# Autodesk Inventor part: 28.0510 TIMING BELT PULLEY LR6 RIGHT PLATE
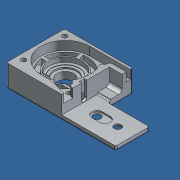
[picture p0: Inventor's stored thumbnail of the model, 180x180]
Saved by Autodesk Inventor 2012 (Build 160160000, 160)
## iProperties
Created: 2007-06
Part Number: 28.0510 TIMING BELT PULLEY LR6 RIGHT PLATE
Document SubType Name: Modeling
Designer: Andy Moles
Material: Aluminum-6061
Mass: 286.09 g
Surface Area: 351.443 cm^2
Volume: 105.568 cm^3
Density: 2.71 g/cm^3
Author: Andy Moles
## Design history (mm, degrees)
sketch "Sketch1"
  geometry: L1 (-35, -39.5)-(-35, 34); L2 (-35, 34)-(51, 34); L3 (51, 34)-(51, 3); L4 (51, 3)-(103, 3); L5 (103, 3)-(103, -39.5); L6 (103, -39.5)-(-35, -39.5); C1 r 10.5 at (0, 0); C2 r 4.5 at (83, -17); C3 r 4.5 at (57, -17); C4 r 3.1 at (-27, 26); C5 r 3.1 at (27, 22.5); C6 r 3.1 at (-27, -26); C7 r 3.1 at (27, -22.5); 1 further point
  constraints: 12 end point, 7 centre point, 4 parallel, 2 vertical alignment, 1 coincident, 1 horizontal alignment, 1 perpendicular, 1 vertical
  dimensions: "d0" = 73.5 distance of L1.start L1.end; "d1" = 138 distance of L5.end L1.start; "d2" = 86 distance of L1.end L2.end; "d3" = 42.5 distance of L4.end L5.end; "d4" = 21 diameter of C1; "d5" = 35 distance from line of point (0, 0) L1; "d6" = 39.5 distance from line of point (0, 0) L6; "d7" = 9 diameter of C3; "d8" = 9 diameter of C2; "d9" = 22.5 distance from line of L6 C2.centre; "d10" = 6.2 diameter of C7; "d11" = 6.2 diameter of C5; "d12" = 6.2 diameter of C4; "d13" = 6.2 diameter of C6; "d14" = 20 distance from line of C2.centre L5; "d15" = 26 distance of C3.centre C2.centre; "d16" = 17 distance from line of L6 C7.centre; "d17" = 45 distance of C5.centre C7.centre; "d18" = 13.5 distance from line of C6.centre L6; "d19" = 52 distance of C4.centre C6.centre; "d20" = 54 horizontal distance of C5.centre C4.centre; "d21" = 8 distance from line of C4.centre L1
extrude "Extrusion1" new body sketch "Sketch1" distance "d22" = 28.5; taper "d23" = 0 deg
hole "Hole1" diameter "d26" = 8; stored, may be unused: countersink angle "d30" = 90 deg, drill point angle "d32" = 118 deg; dims "d24" = 10, "d25" = 10, "d27" = 6, "d28" = 17.5, "d29" = 2, "d31" = 8
hole "Hole2" diameter "d35" = 8; stored, may be unused: countersink angle "d39" = 90 deg, drill point angle "d41" = 118 deg; dims "d33" = 10, "d34" = 10, "d36" = 6, "d37" = 17.5, "d38" = 2, "d40" = 8
sketch "Sketch2"
  geometry: L1 (51, 34)-(51, 3) reference; L2 (-27, 31.976)-(-21.825, 28.988); L3 (-21.825, 28.988)-(-21.825, 23.012); L4 (-21.825, 23.012)-(-27, 20.024); L5 (-27, 20.024)-(-32.175, 23.012); L6 (-32.175, 23.012)-(-32.175, 28.988); L7 (-32.175, 28.988)-(-27, 31.976); L8 (32.175, 19.512)-(27, 16.524); L9 (27, 28.476)-(32.175, 25.488); L10 (21.825, 25.488)-(27, 28.476); L11 (21.825, 19.512)-(21.825, 25.488); L12 (27, 16.524)-(21.825, 19.512); L13 (32.175, 25.488)-(32.175, 19.512); L14 (-21.825, -28.988)-(-27, -31.976); L15 (-21.825, -23.012)-(-21.825, -28.988); L16 (-27, -20.024)-(-21.825, -23.012); L17 (-32.175, -23.012)-(-27, -20.024); L18 (-32.175, -28.988)-(-32.175, -23.012); L19 (-27, -31.976)-(-32.175, -28.988); L20 (32.175, -25.488)-(27, -28.476); L21 (32.175, -19.512)-(32.175, -25.488); L22 (27, -16.524)-(32.175, -19.512); L23 (21.825, -19.512)-(27, -16.524); L24 (21.825, -25.488)-(21.825, -19.512); L25 (27, -28.476)-(21.825, -25.488); C1 r 3.1 at (27, -22.5) reference; C2 r 3.1 at (-27, -26) reference; C3 r 3.1 at (27, 22.5) reference; C4 r 3.1 at (-27, 26) reference; 4 further points
  constraints: 48 end point, 20 equal length, 12 horizontal alignment, 4 midpoint, 4 vertical alignment, 1 parallel
  dimensions: "d42" = 10.35 distance between parallel lines of L4 L7; "d43" = 120 deg angle of L2 L7; "d44" = 10.35 distance between parallel lines of L8 L10; "d45" = 120 deg angle of L9 L10; "d46" = 120 deg angle of L13 L9; "d47" = 10.35 distance between parallel lines of L14 L17; "d48" = 120 deg angle of L16 L17; "d49" = 120 deg angle of L15 L16; "d50" = 10.35 distance between parallel lines of L20 L23; "d51" = 120 deg angle of L22 L23; "d52" = 120 deg angle of L21 L22
extrude "Extrusion2" cut sketch "Sketch2" distance "d53" = 6.1; taper "d54" = 0 deg
sketch "Sketch3"
  geometry: C1 r 10.5 at (0, 0) reference; C2 r 14.3 at (0, 0)
  constraints: 1 centre point, 1 coincident
  dimensions: "d55" = 28.6 diameter of C2
extrude "Extrusion3" cut sketch "Sketch3" distance "d56" = 19.5; taper "d57" = 0 deg
sketch "Sketch4"
  geometry: C1 r 14.3 at (0, 0) reference; C2 r 17.5 at (0, 0)
  constraints: 1 centre point, 1 coincident
  dimensions: "d58" = 35 diameter of C2
extrude "Extrusion4" cut sketch "Sketch4" distance "d59" = 17.5; taper "d60" = 0 deg
sketch "Sketch5"
  geometry: C1 r 17.5 at (0, 0) reference; C2 r 21 at (0, 0)
  constraints: 1 centre point, 1 coincident
  dimensions: "d61" = 42 diameter of C2
extrude "Extrusion5" cut sketch "Sketch5" distance "d62" = 17; taper "d63" = 0 deg
sketch "Sketch6"
  geometry: L1 (35, -39.5)-(35, 34) reference; L2 (-51, 34)-(-51, 3) reference; L3 (-51, 3)-(-103, 3) reference; L4 (-103, 3)-(-103, -39.5) reference; L5 (-103, -39.5)-(35, -39.5) reference; L6 (-51, 20.5)-(-35, 20.5); L7 (-35, 20.5)-(-35, -39.5); C1 r 4.5 at (-57, -17) reference; C2 r 4.5 at (-83, -17) reference
  constraints: 4 end point, 2 point on line, 1 parallel, 1 perpendicular
  dimensions: "d64" = 70 distance between parallel lines of L7 L1; "d65" = 60 distance between parallel lines of L5 L6
extrude "Extrusion6" cut sketch "Sketch6" distance "d66" = 22.5; taper "d67" = 0 deg
fillet "Fillet1" dims "d68" = 2
sketch "Sketch7"
  geometry: L1 (0, 0)-(22.5, 0) reference; L2 (0, -17.5)-(-4, -17.5) reference; L3 (0, -17.5)-(0, -15.5) reference; L4 (2.5, -14.5)-(2.5, -4.5); L5 (0, -15.842)-(0, 0); L6 (0, 0)-(7, 0); A1 r 3 centre (2.5, -17.5) between (2.5, -14.5) and (-0.5, -17.5); A2 r 4.5 centre (7, -4.5) between (7, 0) and (2.5, -4.5); 1 further point
  constraints: 6 end point, 5 point on circle, 3 point on line, 3 tangent, 2 centre point, 2 collinear, 1 horizontal alignment, 1 parallel, 1 vertical alignment
  dimensions: "d69" = 6 diameter of A1; "d70" = 2.5 distance from line of L3 A1.centre; "d71" = 9 diameter of A2
extrude "Extrusion7" join sketch "Sketch7" distance "d72" = 16; taper "d73" = 0 deg
sketch "Sketch8"
  geometry: L1 (-66.982, -10.307)-(-57, -10.307); L2 (-66.982, -23.693)-(-57, -23.693); C1 r 4.5 at (-57, -17) reference; A1 r 6.693 centre (-57, -17) between (-57, -23.693) and (-57, -10.307); A2 r 6.693 centre (-66.982, -17) between (-66.982, -10.307) and (-66.982, -23.693); 1 further point
  constraints: 4 end point, 4 point on circle, 3 tangent, 2 centre point, 1 coincident, 1 horizontal, 1 parallel
  dimensions: "d75" = 13.3858 diameter of A1; "d76" = 13.3858 diameter of A2 (= d75); "d77" = 23.368 dimension on A1 A2
extrude "Extrusion8" cut sketch "Sketch8" distance "d78" = 2; taper "d79" = 0 deg
sketch "Sketch9"
  geometry: L1 (-51, 32)-(-51, 20.5) reference; L2 (-51, 20.5)-(-35, 20.5) reference; L3 (-35, 20.5)-(-35, -39.5) reference; L4 (-35, -39.5)-(33, -39.5) reference; L5 (0, 31)-(-51, 31); L6 (0, -31)-(-12.5, -31); L7 (-35, -37)-(-12.5, -31); L8 (-51, 25.8)-(-33.093, 25.8); L9 (33, 34)-(-49, 34) reference; L10 (-30.1, -22.5)-(-30.1, -22.1); L11 (-35, -25.6)-(-33.6, -25.6); C1 r 21 at (0, 0) reference; A1 r 3.1 centre (-27, 22.5) between (-30.096, 22.652) and (-28.263, 19.669) reference; A2 r 3.1 centre (-27, -22.5) between (-30.1, -22.5) and (-28.263, -19.669) reference; A3 r 3 centre (-29.486, -16.929) between (-28.263, -19.669) and (-26.884, -15.436); A4 r 3 centre (-29.486, 16.929) between (-26.884, 15.436) and (-28.263, 19.669); A5 r 3 centre (-33.093, 22.8) between (-30.096, 22.652) and (-33.093, 25.8); A6 r 3.109 centre (-33.093, 22.8) between (-35.184, 20.5) and (-35, 20.345); A7 r 31 centre (0, 0) between (-26.884, 15.436) and (-26.884, -15.436); A8 r 31 centre (0, 0) between (0, -31) and (0, 31); A9 r 3.5 centre (-33.6, -22.1) between (-33.6, -25.6) and (-30.1, -22.1)
  constraints: 18 point on circle, 12 end point, 11 tangent, 7 centre point, 6 point on line, 3 perpendicular, 2 parallel, 1 coincident
  dimensions: "d81" = 2.5 distance from line of L7.start L4; "d82" = 22.5 distance from line of L6.end L3; "d84" = 6 diameter of A3; "d85" = 6 diameter of A4; "d88" = 3 radius of A5; "d89" = 0.2 distance edge to line of A1 L8; "d90" = 31 radius of A8; "d91" = 31 radius of A7; "d155" = 13.9 distance between parallel lines of L11 L4; "d156" = 3.5 radius of A9
extrude "Extrusion9" cut sketch "Sketch9" distance "d92" = 11; taper "d93" = 0 deg
sketch "Sketch11"
  geometry: L1 (0, -2)-(26.5, -2) reference; L2 (28.5, 0)-(28.5, 69.5) reference; C1 r 2.05 at (19, 26); 1 further point
  constraints: 1 centre point
  dimensions: "d96" = 4.1 diameter of C1; "d97" = 9.5 distance from line of C1.centre L2; "d98" = 28 distance from line of C1.centre L1
extrude "Extrusion10" cut sketch "Sketch11" stored distance "d99" = 11; taper "d100" = 0 deg
hole "Hole3" diameter "d103" = 6.5; stored, may be unused: countersink angle "d107" = 90 deg, drill point angle "d109" = 0 deg; dims "d101" = 10, "d102" = 10, "d104" = 6, "d105" = 17.5, "d106" = 2, "d108" = 25
sketch "Sketch12"
  geometry: L1 (-26, -15.031)-(-10, -15.031); L2 (-10, -15.031)-(-10, -8.031); L3 (-10, -8.031)-(-26, -8.031); L4 (-26, -8.031)-(-26, -15.031); L5 (-10, -9.512)-(-10, -13.55) reference; L6 (-35, 20.5)-(-35, -28.769) reference; 3 further points
  constraints: 8 end point, 3 midpoint, 2 parallel, 1 horizontal, 1 horizontal alignment, 1 perpendicular
  dimensions: "d110" = 7 distance of L3.end L1.start; "d111" = 9 distance between parallel lines of L4 L6
extrude "Extrusion11" cut sketch "Sketch12" distance "d112" = 8; taper "d113" = 0 deg
sketch "Sketch10" dims "d94" = 57, "d95" = 45
  geometry: L1 (0, 31)-(-51, 31) reference; L2 (-20.408, 9.473)-(-25.621, 12.483); L3 (-27.997, -5.331)-(-21.859, -5.331); L4 (-27.191, 14.887)-(-30.922, 16.929); L5 (3.869, 22.165)-(5.426, 27.979); L6 (-26, -8.031)-(-19.404, -8.031) reference; L7 (-18.408, 12.938)-(-23.621, 15.947); L8 (-23.015, 10.978)-(-21.015, 14.442); L9 (-24.682, 14.25)-(0, 0); L10 (7.732, 21.13)-(9.29, 26.943); L11 (4.647, 25.072)-(8.511, 24.037); L12 (0, 0)-(7.376, 27.529); L13 (22.411, 2)-(28.43, 2); L14 (22.411, -2)-(28.43, -2); L15 (25.42, -2)-(25.42, 2); L16 (0, 0)-(28.5, 0); L17 (4.647, -25.072)-(8.511, -24.037); L18 (6.579, -24.554)-(0, 0); L19 (3.869, -22.165)-(5.426, -27.979); L20 (7.732, -21.13)-(9.29, -26.943); L21 (-22.313, -17.731)-(-13.851, -17.731); L22 (-14.665, -15.031)-(-26, -15.031) reference; A1 r 31 centre (0, 0) between (-26.884, 15.436) and (-26.884, -15.436) reference; A2 r 31 centre (0, 0) between (0, -31) and (0, 31) reference; 4 further points
  constraints: 38 end point, 12 midpoint, 8 parallel, 3 point on line, 2 coincident, 2 perpendicular, 1 horizontal, 1 point on circle, 27 other
  dimensions: "d114" = 2.7 distance between parallel lines of L3 L6; "d116" = 4 distance between parallel lines of L7 L2; "d117" = 4 distance from line of L10 L5.end; "d118" = 4 distance of L14.end L13.end; "d119" = 75 deg angle of L16 L12; "d121" = 75 deg angle of L16 L18 (= d119); "d122" = 4 distance between parallel lines of L20 L19; "d123" = 2.7 distance between parallel lines of L22 L21; "d124" = 75 deg angle of L12 L9 (= d119)
extrude "Extrusion12" cut sketch "Sketch10" distance "d125" = 7.5; taper "d126" = 0 deg
sketch "Sketch13"
  geometry: L1 (26.866, -9.512)-(20.391, -9.512) reference; L2 (28.43, -2)-(22.411, -2) reference; L3 (15.819, -16)-(23.585, -16); L4 (21.383, -7)-(27.627, -7); L5 (18.009, -13.488)-(25.106, -13.488) reference; A1 r 28.5 centre (0, 0) between (26.866, -9.512) and (28.43, -2) reference; A2 r 22.5 centre (0, 0) between (20.391, -9.512) and (22.411, -2) reference; A3 r 22.5 centre (0, 0) between (7.732, -21.13) and (18.009, -13.488) reference; A4 r 28.5 centre (0, 0) between (9.29, -26.943) and (25.106, -13.488) reference; A5 r 22.5 centre (0, 0) between (15.819, -16) and (21.383, -7); A6 r 22.5 centre (0, 0) between (22.411, -2) and (22.5, 0); A7 r 22.487 centre (0, 0) between (-17.993, -13.488) and (-15.801, -16); A8 r 28.5 centre (0, 0) between (28.5, 0) and (9.29, -26.943); A9 r 28.5 centre (0, 0) between (23.585, -16) and (27.627, -7)
  constraints: 19 point on circle, 5 centre point, 5 end point, 2 coincident, 2 parallel, 2 point on line
  dimensions: "d128" = 9 distance between parallel lines of L4 L3; "d129" = 3.97618 distance between parallel lines of L5 L1 (derived); "d130" = 2.51191 distance between parallel lines of L4 L1 (= -0.5 x d129 + 0.5 x d128)
extrude "Extrusion13" join sketch "Sketch13" distance "d131" = 4; taper "d132" = 0 deg
hole "Hole4" diameter "d135" = 4.1; stored, may be unused: countersink angle "d139" = 90 deg, drill point angle "d141" = 118 deg; dims "d133" = 10, "d134" = 10, "d136" = 6, "d137" = 17.5, "d138" = 2, "d140" = 25
sketch "Sketch15"
  geometry: L1 (27, -16.524)-(32.175, -19.512) reference; L2 (32.175, -19.512)-(32.175, -16.524); L3 (21.825, -19.512)-(27, -16.524) reference; L4 (-33, -37.5)-(-33, 32) reference; L5 (25.675, -17.289)-(25.675, -16.524); L6 (32.175, -16.524)-(25.675, -16.524)
  constraints: 6 end point, 2 point on line, 1 parallel, 1 perpendicular, 1 vertical
  dimensions: "d146" = 6.5 distance of L2.end L5.end
extrude "Extrusion14" cut sketch "Sketch15" distance "d144" = 6.1; taper "d145" = 0 deg
sketch "Sketch16"
  geometry: L1 (6.1, 8.963)-(0, 8.963) reference; L2 (6.1, 8.963)-(6.1, 18.512); L3 (6.1, 18.512)-(-6.143, 18.512); L4 (-6.143, 18.512)-(-8.9, 13.738); L5 (-8.9, 13.738)-(-6.143, 8.963); L6 (6.1, -2.988)-(0, -2.988) reference; L7 (-6.143, 8.963)-(6.1, 8.963); 1 further point
  constraints: 10 end point, 2 perpendicular, 1 collinear, 1 equal length, 1 horizontal alignment, 1 vertical alignment
  dimensions: "d147" = 21.5 distance between parallel lines of L3 L6; "d148" = 120 deg angle of L5 L4; "d149" = 15 distance from line of L4.end L2
extrude "Extrusion15" cut sketch "Sketch16" distance "d150" = 6.5; taper "d151" = 0 deg
sketch "Sketch17"
  geometry: L1 (22.5, 60)-(22.5, 10.731) reference; L2 (3.5, 31.35)-(22.5, 31.35); L3 (3.5, 24.65)-(22.5, 24.65); L4 (22.5, 31.35)-(22.5, 24.65); C1 r 3.25 at (3.5, 28) reference; A1 r 3.35 centre (3.5, 28) between (3.5, 31.35) and (3.5, 24.65); 1 further point
  constraints: 6 end point, 2 point on circle, 2 point on line, 2 tangent, 1 centre point, 1 coincident, 1 collinear, 1 parallel, 1 perpendicular
  dimensions: "d152" = 3.35 radius of A1
extrude "Extrusion16" cut sketch "Sketch17" distance "d153" = 3; taper "d154" = 0 deg
mirror "Mirror1"
body "Solid1"
other parameters: "d80" = 62, "d87" = 6
